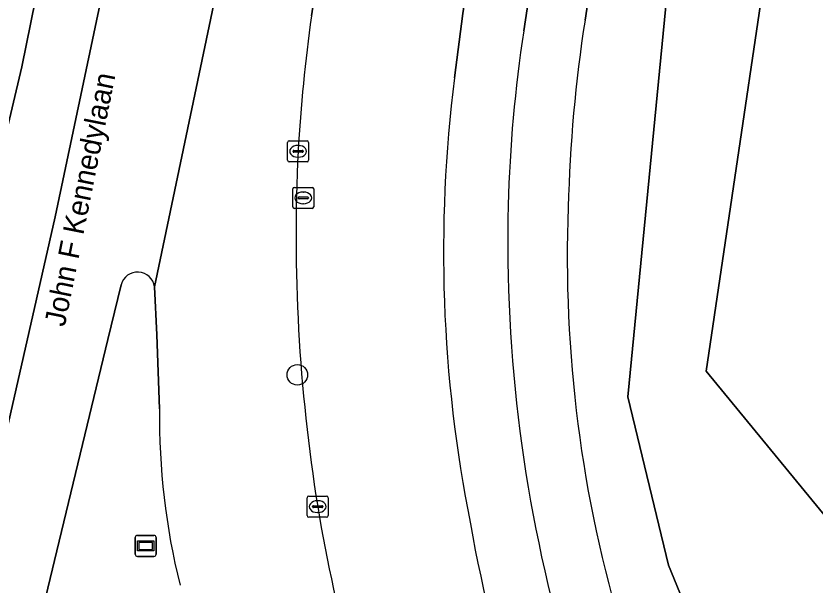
# Model space of a CAD drawing. Extents: x 161758 to 162722, y 384793 to 385405.
# Drawn here: x 161821.75 to 161859.86, y 384934.64 to 384961.76 of the extents above; entities that cross this region are included whole.
import ezdxf

# ---------------------------------------------------------------- set-up
doc = ezdxf.new("R2010")
doc.units = 0
for name, color, linetype in [('IMGEO_Berm_groen', 7, 'Continuous'), ('IMGEO_Boom', 7, 'Continuous'), ('IMGEO_Erf', 7, 'Continuous'), ('IMGEO_Fietspad_open', 7, 'Continuous'), ('IMGEO_Groenvoorziening', 7, 'Continuous'), ('IMGEO_Hek', 7, 'Continuous'), ('IMGEO_Kolk', 7, 'Continuous'), ('IMGEO_Openbare_ruimte_label', 7, 'Continuous'), ('IMGEO_Rijbaan_lokaal_open', 7, 'Continuous'), ('IMGEO_Rijbaan_regionaal_gesloten', 7, 'Continuous'), ('IMGEO_Rioolput', 7, 'Continuous'), ('IMGEO_Verkeersbord', 7, 'Continuous'), ('IMGEO_Voetpad_open', 7, 'Continuous')]:
    doc.layers.add(name, color=color, linetype=linetype)

msp = doc.modelspace()

# ---------------------------------------------------------------- linework, layer by layer
at = {"layer": 'IMGEO_Berm_groen'}
for points in [[(161842.635, 384958.805), (161843.029, 384961.875), (161848.422, 384997.787), (161862.222, 385089.066)], [(161853.937, 385084.588), (161853.743, 385082.758), (161852.871, 385075.308), (161851.83, 385067.734), (161851.205, 385063.4), (161848.122, 385043.24), (161844.782, 385021.036), (161841.441, 384998.802), (161837.654, 384973.607), (161835.818, 384961.758)], [(161826.755, 384948.946), (161826.126, 384946.341), (161820.936, 384924.881), (161816.113, 384906.346), (161812.623, 384894.009), (161812.619, 384893.993), (161813.993, 384893.953), (161813.881, 384892.115), (161826.975, 384891.388)], [(161828.58, 384943.04), (161828.448, 384946.557), (161828.34, 384948.844)]]:
    msp.add_lwpolyline(points, dxfattribs=at)
for centre, radius, start, end in [((161920.079, 384950.246), 85.044, 172.22009, 176.58744), ((161908.469, 384950.514), 66.354, 172.82172, 191.25929), ((161916.576, 384951.299), 81.489, 177.17995, 189.12687), ((161827.538, 384948.747), 0.808, 6.9129, 165.7229), ((161861.718, 384942.647), 33.14, 179.3205, 193.9852), ((161916.432, 384951.785), 81.425, 189.48086, 200.7651), ((161917.724, 384950.873), 75.515, 190.15531, 205.63495)]:
    msp.add_arc(centre, radius, start, end, dxfattribs=at)
at = {"layer": 'IMGEO_Boom'}
msp.add_circle((161835.15, 384944.655), 0.489, dxfattribs=at)
at = {"layer": 'IMGEO_Erf'}
msp.add_lwpolyline([(161880.923, 385119.329), (161863.287, 385003.273), (161862.79, 385000), (161854.635, 384944.828), (161890.389, 384901.27), (161895.384, 384909.442)], dxfattribs=at)
at = {"layer": 'IMGEO_Fietspad_open'}
for points in [[(161873.913, 385143.131), (161885.4, 385214.936), (161882.409, 385215.357), (161881.319, 385208.219), (161867.535, 385122.216), (161862.222, 385089.066), (161848.422, 384997.787), (161843.029, 384961.875), (161842.635, 384958.805)], [(161845.937, 384961.055), (161864.377, 385082.843), (161870.503, 385121.575), (161873.913, 385143.131)]]:
    msp.add_lwpolyline(points, dxfattribs=at)
for centre, radius, start, end in [((161911.921, 384950.991), 66.747, 171.32837, 178.49539), ((161908.469, 384950.514), 66.354, 172.82172, 191.25929), ((161915.606, 384950.977), 70.431, 178.56221, 196.1434), ((161917.724, 384950.873), 75.515, 190.15531, 205.63495)]:
    msp.add_arc(centre, radius, start, end, dxfattribs=at)
at = {"layer": 'IMGEO_Groenvoorziening'}
for points in [[(161892.743, 385260.68), (161890.539, 385233.713), (161888.572, 385218.345), (161891.617, 385217.57), (161876.429, 385120.298), (161873.599, 385102.176), (161860.843, 385019.372), (161853.315, 384968.451), (161850.889, 384943.599), (161852.833, 384935.577), (161860.083, 384917.83), (161874.638, 384901.508), (161887.186, 384893.396), (161890.389, 384901.27), (161854.635, 384944.828), (161862.79, 385000), (161863.287, 385003.273), (161880.923, 385119.329), (161887.975, 385165.729), (161892.13, 385191.383), (161913.18, 385282.726), (161913.347, 385283.925), (161913.577, 385286.213)], [(161891.617, 385217.57), (161888.572, 385218.345), (161888.19, 385214.465), (161881.5, 385172.372), (161876.704, 385142.872), (161873.252, 385120.982), (161867.164, 385082.371), (161848.857, 384961.566)], [(161885.599, 384889.495), (161887.186, 384893.396), (161874.638, 384901.508), (161860.083, 384917.83), (161852.833, 384935.577), (161850.889, 384943.599), (161853.315, 384968.451), (161860.843, 385019.372), (161873.599, 385102.176), (161876.429, 385120.298), (161891.617, 385217.57)]]:
    msp.add_lwpolyline(points, dxfattribs=at)
for centre, radius, start, end in [((161917.156, 384950.951), 69.119, 171.16618, 178.59101), ((161910.154, 384950.229), 62.143, 177.76622, 196.86974)]:
    msp.add_arc(centre, radius, start, end, dxfattribs=at)
at = {"layer": 'IMGEO_Hek'}
msp.add_lwpolyline([(161890.389, 384901.27), (161854.635, 384944.828), (161862.79, 385000)], dxfattribs=at)
at = {"layer": 'IMGEO_Kolk'}
for p, q in [((161834.685, 384954.882), (161834.685, 384955.734)), ((161834.76, 384955.808), (161835.612, 384955.808)), ((161835.173, 384955.588), (161835.198, 384955.588)), ((161835.686, 384955.734), (161835.686, 384954.882)), ((161834.944, 384955.302), (161834.944, 384955.314)), ((161835.382, 384955.265), (161834.984, 384955.265)), ((161834.987, 384955.351), (161835.385, 384955.351)), ((161835.428, 384955.314), (161835.428, 384955.302)), ((161835.612, 384954.808), (161834.76, 384954.808)), ((161835.196, 384955.028), (161835.171, 384955.028)), ((161835.618, 384937.947), (161835.618, 384938.799)), ((161835.693, 384938.873), (161836.545, 384938.873)), ((161836.619, 384938.799), (161836.619, 384937.947)), ((161835.92, 384938.416), (161836.318, 384938.416)), ((161836.106, 384938.653), (161836.131, 384938.653)), ((161835.877, 384938.367), (161835.877, 384938.379)), ((161836.315, 384938.33), (161835.917, 384938.33)), ((161836.129, 384938.093), (161836.104, 384938.093)), ((161836.361, 384938.379), (161836.361, 384938.367)), ((161836.545, 384937.873), (161835.693, 384937.873))]:
    msp.add_line(p, q, dxfattribs=at)
for points in [[(161834.685, 384954.882), (161834.685, 384955.734)], [(161834.76, 384955.808), (161835.612, 384955.808)], [(161835.686, 384955.734), (161835.686, 384954.882)], [(161835.612, 384954.808), (161834.76, 384954.808)], [(161835.618, 384937.947), (161835.618, 384938.799)], [(161835.693, 384938.873), (161836.545, 384938.873)], [(161836.619, 384938.799), (161836.619, 384937.947)], [(161836.545, 384937.873), (161835.693, 384937.873)]]:
    msp.add_lwpolyline(points, dxfattribs=at)
for centre, radius, start, end in [((161834.762, 384955.732), 0.0765, 91.552, 178.448), ((161834.762, 384955.732), 0.0765, 91.552, 178.448), ((161835.61, 384955.732), 0.0765, 1.552, 88.448), ((161835.61, 384955.732), 0.0765, 1.552, 88.448), ((161834.984, 384955.311), 0.0403, 85.8775, 175.7526), ((161834.981, 384955.301), 0.0366, 178.938, 274.7102), ((161835.385, 384955.308), 0.043, 264.8664, 352.4533), ((161835.389, 384955.313), 0.0386, 1.7309, 96.639), ((161834.762, 384954.884), 0.0765, 181.552, 268.448), ((161834.762, 384954.884), 0.0765, 181.552, 268.448), ((161835.61, 384954.884), 0.0765, 271.552, 358.448), ((161835.61, 384954.884), 0.0765, 271.552, 358.448), ((161835.695, 384938.797), 0.0765, 91.552, 178.448), ((161835.695, 384938.797), 0.0765, 91.552, 178.448), ((161836.543, 384938.797), 0.0765, 1.552, 88.448), ((161836.543, 384938.797), 0.0765, 1.552, 88.448), ((161835.917, 384938.376), 0.0403, 85.8775, 175.7526), ((161836.322, 384938.378), 0.0386, 1.7309, 96.639), ((161835.914, 384938.366), 0.0366, 178.938, 274.7102), ((161836.318, 384938.373), 0.043, 264.8664, 352.4533), ((161835.695, 384937.949), 0.0765, 181.552, 268.448), ((161835.695, 384937.949), 0.0765, 181.552, 268.448), ((161836.543, 384937.949), 0.0765, 271.552, 358.448), ((161836.543, 384937.949), 0.0765, 271.552, 358.448)]:
    msp.add_arc(centre, radius, start, end, dxfattribs=at)
for centre, major_axis, ratio, start_param, end_param in [((161835.172, 384955.308), (-0.387, 0.002), 0.722429, 4.712389, 7.853982), ((161835.197, 384955.308), (-0.39, 0.002), 0.717154, 1.570796, 4.712389), ((161836.105, 384938.373), (-0.387, 0.002), 0.722429, 4.712389, 7.853982), ((161836.13, 384938.373), (-0.39, 0.002), 0.717154, 1.570796, 4.712389)]:
    msp.add_ellipse(centre, major_axis=major_axis, ratio=ratio, start_param=start_param, end_param=end_param, dxfattribs=at)
at = {"layer": 'IMGEO_Rijbaan_lokaal_open'}
for points in [[(161835.818, 384961.758), (161837.654, 384973.607), (161841.441, 384998.802), (161844.782, 385021.036), (161848.122, 385043.24), (161851.205, 385063.4), (161851.83, 385067.734), (161852.871, 385075.308), (161853.743, 385082.758), (161853.937, 385084.588)], [(161841.757, 385025.901), (161833.779, 384973.366), (161833.486, 384973.405), (161828.34, 384948.844), (161828.448, 384946.557), (161828.58, 384943.04)]]:
    msp.add_lwpolyline(points, dxfattribs=at)
for centre, radius, start, end in [((161920.079, 384950.246), 85.044, 172.22009, 176.58744), ((161916.576, 384951.299), 81.489, 177.17995, 189.12687), ((161861.718, 384942.647), 33.14, 179.3205, 193.9852), ((161916.432, 384951.785), 81.425, 189.48086, 200.7651)]:
    msp.add_arc(centre, radius, start, end, dxfattribs=at)
at = {"layer": 'IMGEO_Rijbaan_regionaal_gesloten'}
msp.add_lwpolyline([(161851.137, 385125.739), (161847.678, 385126.475), (161845.742, 385106.666), (161842.993, 385081.473), (161839.52, 385055.945), (161835.903, 385032.779), (161831.569, 385007.397), (161829.399, 384995.814), (161825.492, 384976.413), (161822.019, 384959.327), (161818.724, 384945.388), (161808.45, 384904.992), (161805.49, 384894.455), (161802.858, 384885.087), (161806.301, 384884.91), (161808.959, 384894.325), (161812.031, 384905.208), (161818.108, 384927.94), (161823.605, 384952.19), (161832.136, 384992.657), (161842.706, 385055.699)], close=True, dxfattribs=at)
for points in [[(161849.925, 385105.437), (161851.374, 385125.689), (161851.137, 385125.739), (161842.706, 385055.699), (161832.136, 384992.657), (161823.605, 384952.19), (161818.108, 384927.94), (161812.031, 384905.208), (161808.959, 384894.325), (161806.301, 384884.91), (161810, 384884.72), (161811.52, 384889.999), (161811.584, 384890.221), (161811.803, 384891.061), (161812.619, 384893.993), (161812.623, 384894.009), (161816.113, 384906.346), (161820.936, 384924.881), (161826.126, 384946.341)], [(161822.556, 384979.674), (161816.347, 384950.387), (161814.168, 384941.371), (161810.063, 384925.307), (161808.527, 384919.411), (161805.893, 384909.296), (161803.561, 384900.798), (161802.106, 384895.489), (161801.851, 384894.591), (161801.011, 384891.632), (161800.726, 384890.625), (161799.208, 384885.274), (161802.858, 384885.087), (161805.49, 384894.455), (161808.45, 384904.992), (161818.724, 384945.388), (161822.019, 384959.327), (161825.492, 384976.413), (161829.399, 384995.814), (161831.569, 385007.397), (161835.903, 385032.779), (161839.52, 385055.945), (161842.993, 385081.473), (161845.742, 385106.666)], [(161828.34, 384948.844), (161833.486, 384973.405), (161841.424, 385025.925)], [(161826.126, 384946.341), (161826.755, 384948.946)]]:
    msp.add_lwpolyline(points, dxfattribs=at)
msp.add_arc((161827.538, 384948.747), 0.808, 6.9129, 165.7229, dxfattribs=at)
at = {"layer": 'IMGEO_Rioolput'}
for p, q in [((161834.932, 384952.663), (161834.932, 384953.515)), ((161835.007, 384953.589), (161835.859, 384953.589)), ((161835.42, 384953.369), (161835.445, 384953.369)), ((161835.933, 384953.515), (161835.933, 384952.663)), ((161835.191, 384953.083), (161835.191, 384953.095)), ((161835.629, 384953.046), (161835.231, 384953.046)), ((161835.234, 384953.132), (161835.632, 384953.132)), ((161835.675, 384953.095), (161835.675, 384953.083)), ((161835.859, 384952.589), (161835.007, 384952.589)), ((161835.443, 384952.809), (161835.418, 384952.809))]:
    msp.add_line(p, q, dxfattribs=at)
for points in [[(161834.932, 384952.663), (161834.932, 384953.515)], [(161835.007, 384953.589), (161835.859, 384953.589)], [(161835.933, 384953.515), (161835.933, 384952.663)], [(161835.859, 384952.589), (161835.007, 384952.589)]]:
    msp.add_lwpolyline(points, dxfattribs=at)
for centre, radius, start, end in [((161835.009, 384953.513), 0.0765, 91.552, 178.448), ((161835.009, 384953.513), 0.0765, 91.552, 178.448), ((161835.857, 384953.513), 0.0765, 1.552, 88.448), ((161835.857, 384953.513), 0.0765, 1.552, 88.448), ((161835.231, 384953.092), 0.0403, 85.8775, 175.7526), ((161835.228, 384953.082), 0.0366, 178.938, 274.7102), ((161835.632, 384953.089), 0.043, 264.8664, 352.4533), ((161835.636, 384953.094), 0.0386, 1.7309, 96.639), ((161835.009, 384952.665), 0.0765, 181.552, 268.448), ((161835.009, 384952.665), 0.0765, 181.552, 268.448), ((161835.857, 384952.665), 0.0765, 271.552, 358.448), ((161835.857, 384952.665), 0.0765, 271.552, 358.448)]:
    msp.add_arc(centre, radius, start, end, dxfattribs=at)
for centre, major_axis, ratio, start_param, end_param in [((161835.419, 384953.089), (-0.387, 0.002), 0.722429, 4.712389, 7.853982), ((161835.444, 384953.089), (-0.39, 0.002), 0.717154, 1.570796, 4.712389)]:
    msp.add_ellipse(centre, major_axis=major_axis, ratio=ratio, start_param=start_param, end_param=end_param, dxfattribs=at)
at = {"layer": 'IMGEO_Verkeersbord'}
for p, q in [((161827.43, 384936.104), (161827.43, 384936.904)), ((161827.43, 384936.904), (161827.43, 384936.104)), ((161827.53, 384937.004), (161828.32, 384937.004)), ((161828.32, 384937.004), (161827.53, 384937.004)), ((161828.42, 384936.904), (161828.42, 384936.104)), ((161828.42, 384936.104), (161828.42, 384936.904)), ((161828.32, 384936.004), (161827.53, 384936.004)), ((161827.53, 384936.004), (161828.32, 384936.004))]:
    msp.add_line(p, q, dxfattribs=at)
for points in [[(161827.531, 384936.736), (161828.319, 384936.736), (161828.319, 384936.272), (161827.531, 384936.272), (161827.531, 384936.736)], [(161827.596, 384936.671), (161827.596, 384936.337), (161828.254, 384936.337), (161828.254, 384936.671), (161827.596, 384936.671)]]:
    msp.add_lwpolyline(points, dxfattribs=at)
for centre, start, end in [((161827.53, 384936.904), 90, 180), ((161827.53, 384936.904), 90, 180), ((161828.32, 384936.904), 0, 90), ((161828.32, 384936.904), 360, 90), ((161827.53, 384936.104), 180, 270), ((161827.53, 384936.104), 180, 270), ((161828.32, 384936.104), 270, 0), ((161828.32, 384936.104), 270, 0)]:
    msp.add_arc(centre, 0.1, start, end, dxfattribs=at)
at = {"layer": 'IMGEO_Voetpad_open'}
for points in [[(161867.164, 385082.371), (161873.252, 385120.982), (161870.503, 385121.575), (161864.377, 385082.843), (161845.937, 384961.055)], [(161848.857, 384961.566), (161867.164, 385082.371)]]:
    msp.add_lwpolyline(points, dxfattribs=at)
for centre, radius, start, end in [((161917.156, 384950.951), 69.119, 171.16618, 178.59101), ((161911.921, 384950.991), 66.747, 171.32837, 178.49539), ((161915.606, 384950.977), 70.431, 178.56221, 196.1434), ((161910.154, 384950.229), 62.143, 177.76622, 196.86974)]:
    msp.add_arc(centre, radius, start, end, dxfattribs=at)

# ---------------------------------------------------------------- texts
at = {"layer": 'IMGEO_Openbare_ruimte_label'}
msp.add_text('John F Kennedylaan', height=1, rotation=78.6339, dxfattribs=at).set_placement((161824.07, 384946.914))

doc.saveas('drawing.dxf')
